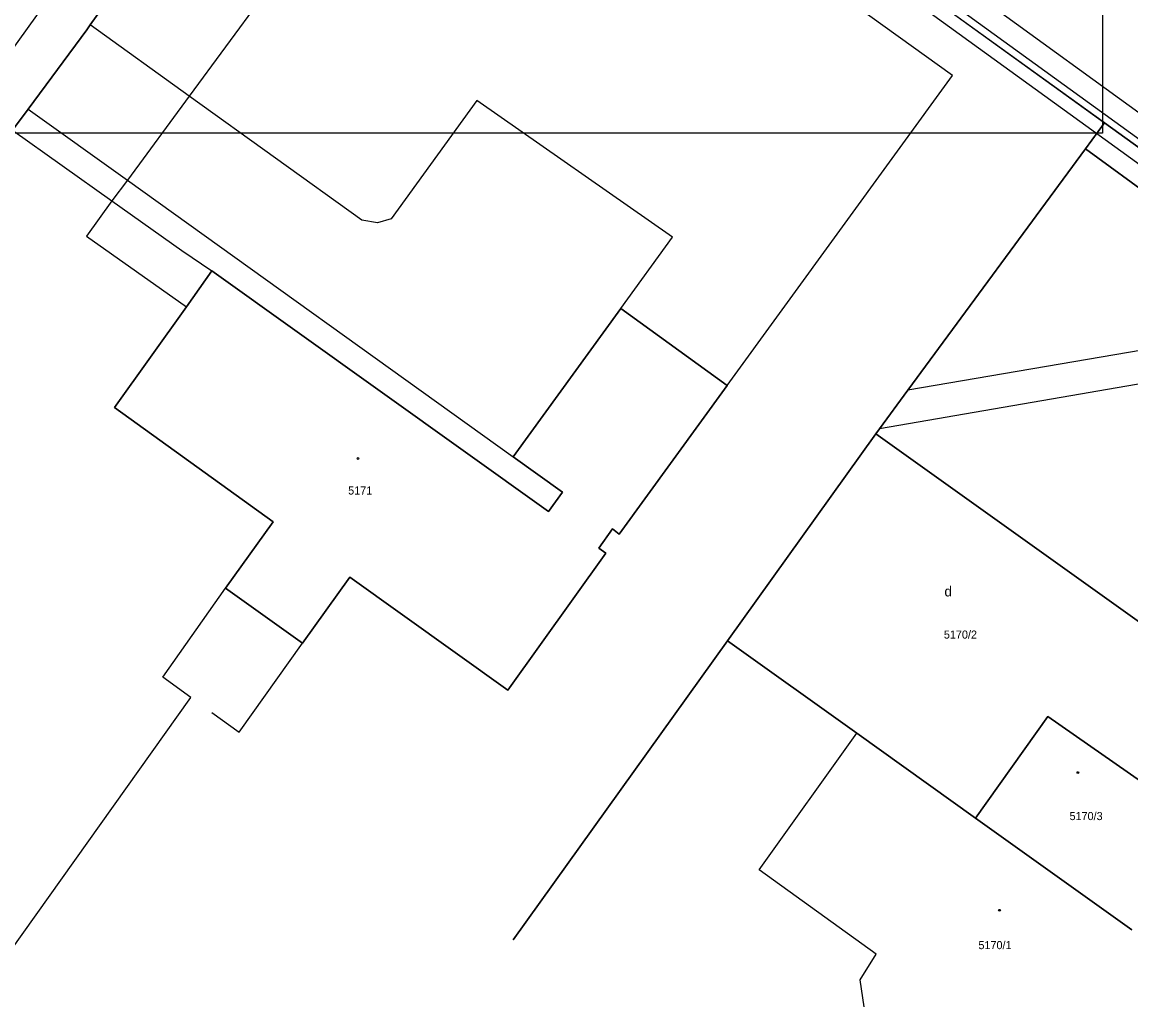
# Model space of a CAD drawing. Extents: x -400488 to -400124, y -1251493 to -1251223.
# Drawn here: x -400314.4 to -400248.8, y -1251492.8 to -1251434.4 of the extents above; entities that cross this region are included whole.
import ezdxf

# ---------------------------------------------------------------- set-up
doc = ezdxf.new("R2010")
doc.units = 0
doc.layers.add('Level 3', color=7, linetype='Continuous')
doc.layers.add('Level 63', color=7, linetype='Continuous')

msp = doc.modelspace()

# ---------------------------------------------------------------- linework, layer by layer
at = {"layer": 'Level 3'}
msp.add_lwpolyline([(-400397.431, -1251233.087), (-400250.431, -1251233.087), (-400250.431, -1251440.987), (-400397.431, -1251440.987)], close=True, dxfattribs=at)
at = {"layer": 'Level 63'}
for p, q in [((-400293.55, -1251410.86), (-400310.42, -1251434.57)), ((-400310.42, -1251434.57), (-400293.55, -1251410.86)), ((-400250.32, -1251440.37), (-400290.8, -1251411.09)), ((-400290.8, -1251411.09), (-400250.32, -1251440.37)), ((-400287.04, -1251411.61), (-400201.09, -1251474.06)), ((-400286.78, -1251413.41), (-400201.79, -1251475.05)), ((-400203.57, -1251475.28), (-400286.46, -1251415.13)), ((-400288.33, -1251416.7), (-400304.56, -1251438.79)), ((-400259.32, -1251437.56), (-400288.33, -1251416.7)), ((-400312.95, -1251433.09), (-400317.46, -1251439.39)), ((-400310.42, -1251434.57), (-400310.61, -1251434.85)), ((-400310.61, -1251434.85), (-400310.42, -1251434.57)), ((-400304.56, -1251438.79), (-400310.42, -1251434.57)), ((-400310.61, -1251434.85), (-400314.1, -1251439.56)), ((-400314.1, -1251439.56), (-400310.61, -1251434.85)), ((-400272.68, -1251455.94), (-400259.32, -1251437.56)), ((-400304.56, -1251438.79), (-400308.2, -1251443.78)), ((-400294.32, -1251446.14), (-400304.56, -1251438.79)), ((-400287.5, -1251439.05), (-400292.58, -1251446.06)), ((-400275.92, -1251447.16), (-400287.5, -1251439.05)), ((-400314.1, -1251439.56), (-400315.03, -1251440.81)), ((-400315.03, -1251440.81), (-400314.1, -1251439.56)), ((-400314.1, -1251439.56), (-400308.2, -1251443.78)), ((-400251.44, -1251441.92), (-400250.32, -1251440.37)), ((-400250.32, -1251440.37), (-400251.44, -1251441.92)), ((-400234.81, -1251451.59), (-400250.32, -1251440.37)), ((-400250.32, -1251440.37), (-400234.81, -1251451.59)), ((-400315.03, -1251440.81), (-400309.14, -1251445)), ((-400251.44, -1251441.92), (-400261.97, -1251456.23)), ((-400261.97, -1251456.23), (-400251.44, -1251441.92)), ((-400237.56, -1251452.06), (-400251.44, -1251441.92)), ((-400251.44, -1251441.92), (-400237.56, -1251452.06)), ((-400308.2, -1251443.78), (-400309.14, -1251445)), ((-400308.2, -1251443.78), (-400285.35, -1251460.18)), ((-400309.14, -1251445), (-400310.64, -1251447.09)), ((-400309.14, -1251445), (-400304.99, -1251447.95)), ((-400293.39, -1251446.31), (-400294.32, -1251446.14)), ((-400292.58, -1251446.06), (-400293.39, -1251446.31)), ((-400310.64, -1251447.09), (-400304.72, -1251451.28)), ((-400278.97, -1251451.38), (-400275.92, -1251447.16)), ((-400304.99, -1251447.95), (-400303.21, -1251449.14)), ((-400303.21, -1251449.14), (-400304.72, -1251451.28)), ((-400304.72, -1251451.28), (-400303.21, -1251449.14)), ((-400283.26, -1251463.42), (-400303.21, -1251449.14)), ((-400303.21, -1251449.14), (-400283.26, -1251463.42)), ((-400304.72, -1251451.28), (-400308.98, -1251457.25)), ((-400308.98, -1251457.25), (-400304.72, -1251451.28)), ((-400278.97, -1251451.38), (-400285.35, -1251460.18)), ((-400285.35, -1251460.18), (-400278.97, -1251451.38)), ((-400272.68, -1251455.94), (-400278.97, -1251451.38)), ((-400278.97, -1251451.38), (-400272.68, -1251455.94)), ((-400237.56, -1251452.06), (-400261.97, -1251456.23)), ((-400235.39, -1251453.65), (-400263.65, -1251458.51)), ((-400279.07, -1251464.75), (-400272.68, -1251455.94)), ((-400272.68, -1251455.94), (-400279.07, -1251464.75)), ((-400261.97, -1251456.23), (-400263.65, -1251458.51)), ((-400263.65, -1251458.51), (-400261.97, -1251456.23)), ((-400308.98, -1251457.25), (-400299.57, -1251464.02)), ((-400299.57, -1251464.02), (-400308.98, -1251457.25)), ((-400263.87, -1251458.81), (-400272.66, -1251471.08)), ((-400272.66, -1251471.08), (-400263.87, -1251458.81)), ((-400263.65, -1251458.51), (-400263.87, -1251458.81)), ((-400263.87, -1251458.81), (-400263.65, -1251458.51)), ((-400228.16, -1251484.33), (-400263.87, -1251458.81)), ((-400263.87, -1251458.81), (-400228.16, -1251484.33)), ((-400285.35, -1251460.18), (-400282.44, -1251462.27)), ((-400282.44, -1251462.27), (-400285.35, -1251460.18)), ((-400282.44, -1251462.27), (-400283.26, -1251463.42)), ((-400283.26, -1251463.42), (-400282.44, -1251462.27)), ((-400299.57, -1251464.02), (-400302.4, -1251467.95)), ((-400302.4, -1251467.95), (-400299.57, -1251464.02)), ((-400280.29, -1251465.58), (-400279.47, -1251464.45)), ((-400279.47, -1251464.45), (-400280.29, -1251465.58)), ((-400279.47, -1251464.45), (-400279.07, -1251464.75)), ((-400279.07, -1251464.75), (-400279.47, -1251464.45)), ((-400279.86, -1251465.89), (-400280.29, -1251465.58)), ((-400280.29, -1251465.58), (-400279.86, -1251465.89)), ((-400285.67, -1251474), (-400279.86, -1251465.89)), ((-400279.86, -1251465.89), (-400285.67, -1251474)), ((-400297.84, -1251471.23), (-400295.03, -1251467.31)), ((-400295.03, -1251467.31), (-400297.84, -1251471.23)), ((-400295.03, -1251467.31), (-400285.67, -1251474)), ((-400285.67, -1251474), (-400295.03, -1251467.31)), ((-400306.12, -1251473.24), (-400302.4, -1251467.95)), ((-400302.4, -1251467.95), (-400297.84, -1251471.23)), ((-400297.84, -1251471.23), (-400302.4, -1251467.95)), ((-400301.59, -1251476.5), (-400297.84, -1251471.23)), ((-400272.66, -1251471.08), (-400285.35, -1251488.8)), ((-400285.35, -1251488.8), (-400272.66, -1251471.08)), ((-400272.66, -1251471.08), (-400265, -1251476.56)), ((-400265, -1251476.56), (-400272.66, -1251471.08)), ((-400304.46, -1251474.44), (-400306.12, -1251473.24)), ((-400317.51, -1251492.77), (-400304.46, -1251474.44)), ((-400303.22, -1251475.34), (-400301.59, -1251476.5)), ((-400257.96, -1251481.59), (-400253.68, -1251475.56)), ((-400253.68, -1251475.56), (-400257.96, -1251481.59)), ((-400253.68, -1251475.56), (-400245.47, -1251481.31)), ((-400245.47, -1251481.31), (-400253.68, -1251475.56)), ((-400270.79, -1251484.66), (-400265, -1251476.56)), ((-400265, -1251476.56), (-400257.96, -1251481.59)), ((-400265, -1251476.56), (-400257.96, -1251481.59)), ((-400257.96, -1251481.59), (-400265, -1251476.56)), ((-400248.7, -1251488.21), (-400257.96, -1251481.59)), ((-400257.96, -1251481.59), (-400248.7, -1251488.21)), ((-400263.85, -1251489.65), (-400270.79, -1251484.66)), ((-400264.79, -1251491.18), (-400263.85, -1251489.65)), ((-400264.55, -1251492.78), (-400264.79, -1251491.18))]:
    msp.add_line(p, q, dxfattribs=at)
for centre in [(-400294.55, -1251460.276), (-400251.89, -1251478.896), (-400256.54, -1251487.056)]:
    msp.add_circle(centre, 0.054, dxfattribs=at)

# ---------------------------------------------------------------- texts
for s, height, p in [('5171', 0.48, (-400295.134, -1251462.41)), ('d', 0.6, (-400259.803, -1251468.45)), ('5170/2', 0.48, (-400259.838, -1251470.95)), ('5170/3', 0.48, (-400252.392, -1251481.71)), ('5170/1', 0.48, (-400257.789, -1251489.36))]:
    msp.add_text(s, height=height, dxfattribs=at).set_placement(p)

doc.saveas('drawing.dxf')
